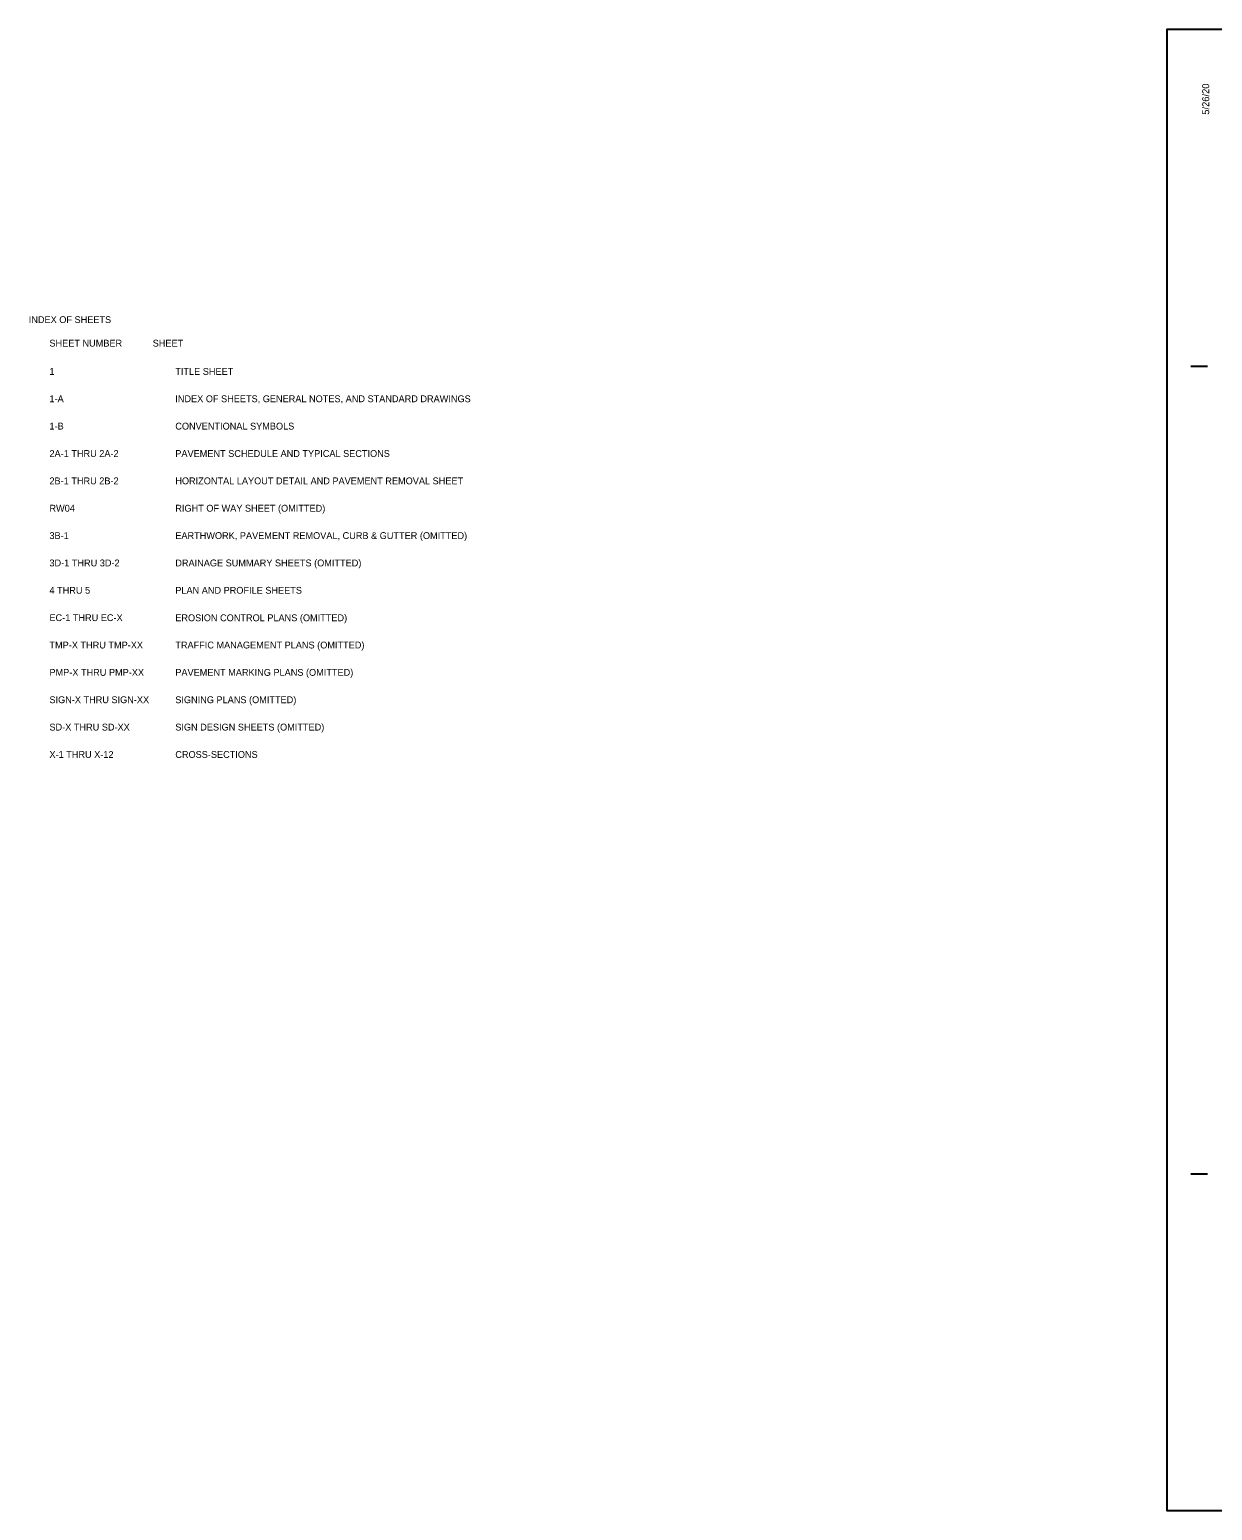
# Model space of a CAD drawing. Extents: x 1844369 to 1844800, y 671424 to 671721.
# Drawn here: x 1844369.5 to 1844443, y 671501.1 to 671593.1 of the extents above; entities that cross this region are included whole.
import ezdxf

# ---------------------------------------------------------------- set-up
doc = ezdxf.new("R2010")
doc.units = 0
for name, color, linetype in [('Sheet Data Text CELL', 7, 'Continuous'), ('Sheet_Clip_Boundary_CELL', 7, 'Continuous'), ('Sheet_Data_Field_CELL', 7, 'Continuous'), ('Sheet_Plan_CELL', 7, 'Continuous')]:
    doc.layers.add(name, color=color, linetype=linetype)

msp = doc.modelspace()

# ---------------------------------------------------------------- linework, layer by layer
at = {"layer": 'Sheet_Clip_Boundary_CELL'}
msp.add_lwpolyline([(1844581.788, 671593.106), (1844440.123, 671593.106), (1844440.123, 671501.068), (1844581.788, 671501.068)], close=True, dxfattribs=at)
at = {"layer": 'Sheet_Data_Field_CELL'}
msp.add_line((1844440.123, 671501.068), (1844440.123, 671501.068), dxfattribs=at)
at = {"layer": 'Sheet_Plan_CELL'}
for p, q in [((1844441.614, 671572.189), (1844442.651, 671572.191)), ((1844441.616, 671521.986), (1844442.652, 671521.985))]:
    msp.add_line(p, q, dxfattribs=at)

# ---------------------------------------------------------------- texts
at = {"layer": 'Sheet Data Text CELL'}
for s, height, p in [('                        INDEX OF SHEETS ', 0.42516, (1844365.632, 671574.867)), ('SHEET NUMBER            SHEET   ', 0.42516, (1844370.707, 671573.404)), ('1', 0.425, (1844370.707, 671571.648)), ('TITLE SHEET', 0.42516, (1844378.526, 671571.648)), ('1-A', 0.4252, (1844370.707, 671569.948)), ('INDEX OF SHEETS, GENERAL NOTES, AND STANDARD DRAWINGS', 0.42516, (1844378.526, 671569.948)), ('1-B', 0.4252, (1844370.707, 671568.247)), ('CONVENTIONAL SYMBOLS ', 0.42516, (1844378.526, 671568.247)), ('2A-1 THRU 2A-2', 0.42516, (1844370.707, 671566.546)), ('PAVEMENT SCHEDULE AND TYPICAL SECTIONS', 0.42516, (1844378.526, 671566.546)), ('2B-1 THRU 2B-2', 0.42516, (1844370.707, 671564.846)), ('HORIZONTAL LAYOUT DETAIL AND PAVEMENT REMOVAL SHEET', 0.42516, (1844378.526, 671564.846)), ('RW04', 0.4252, (1844370.707, 671563.145)), ('RIGHT OF WAY SHEET (OMITTED)', 0.42516, (1844378.526, 671563.145)), ('3B-1', 0.4252, (1844370.707, 671561.444)), ('EARTHWORK, PAVEMENT REMOVAL, CURB & GUTTER (OMITTED)', 0.42516, (1844378.526, 671561.444)), ('3D-1 THRU 3D-2', 0.42516, (1844370.707, 671559.744)), ('DRAINAGE SUMMARY SHEETS (OMITTED)', 0.42516, (1844378.526, 671559.744)), ('4 THRU 5', 0.4252, (1844370.707, 671558.043)), ('PLAN AND PROFILE SHEETS', 0.42516, (1844378.526, 671558.043)), ('EC-1 THRU EC-X', 0.42516, (1844370.707, 671556.342)), ('X-1 THRU X-12', 0.42516, (1844370.707, 671547.839)), ('CROSS-SECTIONS', 0.42516, (1844378.526, 671547.839))]:
    msp.add_text(s, height=height, dxfattribs=at).set_placement(p)
for s, p in [('EROSION CONTROL PLANS (OMITTED)', (1844378.526, 671556.334)), ('TMP-X THRU TMP-XX', (1844370.707, 671554.642)), ('TRAFFIC MANAGEMENT PLANS (OMITTED)', (1844378.526, 671554.642)), ('PMP-X THRU PMP-XX', (1844370.707, 671552.941)), ('PAVEMENT MARKING PLANS (OMITTED)', (1844378.526, 671552.941)), ('SIGN-X THRU SIGN-XX', (1844370.707, 671551.241)), ('SIGNING PLANS (OMITTED)', (1844378.526, 671551.241)), ('SD-X THRU SD-XX', (1844370.707, 671549.54)), ('SIGN DESIGN SHEETS (OMITTED)', (1844378.526, 671549.54))]:
    msp.add_text(s, height=0.42516, rotation=360, dxfattribs=at).set_placement(p)
at = {"layer": 'Sheet_Plan_CELL'}
msp.add_text('5/26/20', height=0.4351, rotation=90, dxfattribs=at).set_placement((1844442.758, 671587.815))

doc.saveas('drawing.dxf')
